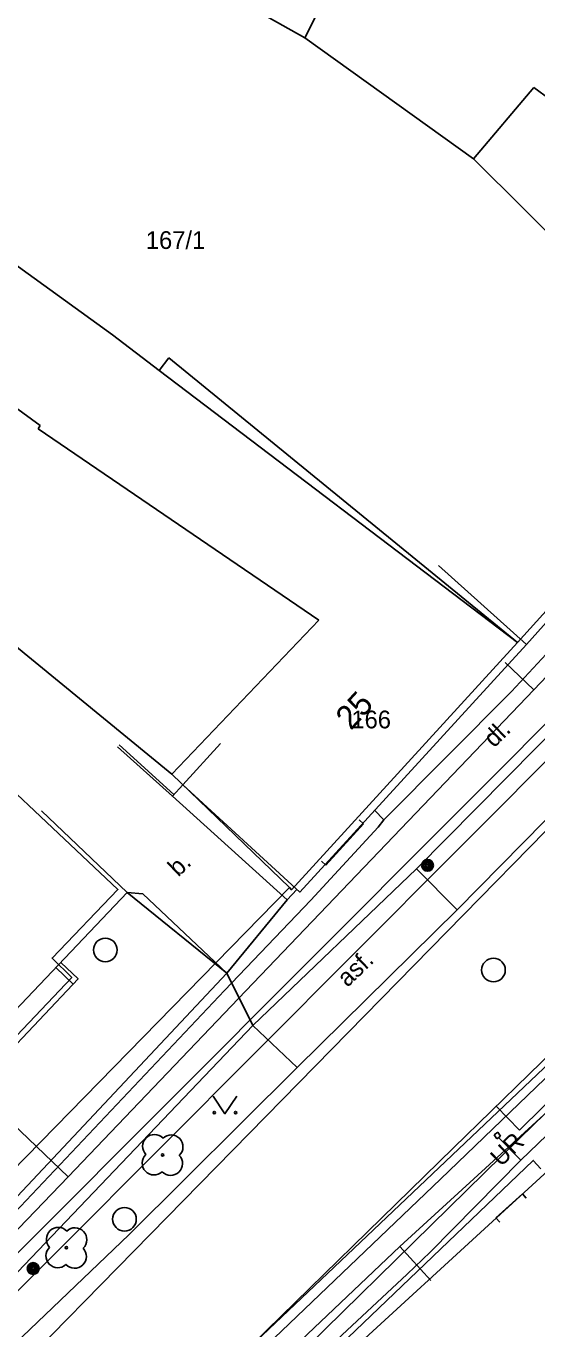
# Model space of a CAD drawing. Extents: x -601580 to 4, y -1204314 to 4.
# Drawn here: x -600441.7 to -600420.1, y -1203687.1 to -1203632.1 of the extents above; entities that cross this region are included whole.
import ezdxf

# ---------------------------------------------------------------- set-up
doc = ezdxf.new("R2010")
doc.units = 0
for name, color, linetype in [('00-INNOGY-NTL', 7, 'Continuous'), ('00-KN-HRANICE PARCEL', 7, 'Continuous'), ('00-KN-PARC. CISLA', 7, 'Continuous'), ('00-KN-VNITRNI KRESBA', 7, 'Continuous'), ('00-POLOHOPIS', 7, 'Continuous'), ('00-SITE KOM. KABEL', 7, 'Continuous'), ('00-VAK-VODA-RAD IGIS', 7, 'Continuous'), ('Vrstva 22', 7, 'Continuous'), ('Vrstva 25', 7, 'Continuous'), ('Vrstva 27', 7, 'Continuous'), ('Vrstva 36', 7, 'Continuous'), ('Vrstva 6', 7, 'Continuous')]:
    doc.layers.add(name, color=color, linetype=linetype)

# ---------------------------------------------------------------- blocks, each defined once
blk = doc.blocks.new('6.01A_68')
at = {"layer": 'Vrstva 25'}
for radius in [0.25, 0.2, 0.15, 0.1, 0.05]:
    blk.add_circle((0, 0), radius, dxfattribs=at)
blk = doc.blocks.new('6.01A_70')
at = {"layer": 'Vrstva 25'}
for radius in [0.25, 0.2, 0.15, 0.1, 0.05]:
    blk.add_circle((0, 0), radius, dxfattribs=at)
blk = doc.blocks.new('6.01A_72')
at = {"layer": 'Vrstva 25'}
for radius in [0.25, 0.2, 0.15, 0.1, 0.05]:
    blk.add_circle((0, 0), radius, dxfattribs=at)
blk = doc.blocks.new('6.01A_74')
at = {"layer": 'Vrstva 25'}
for radius in [0.25, 0.2, 0.15, 0.1, 0.05]:
    blk.add_circle((0, 0), radius, dxfattribs=at)
blk = doc.blocks.new('VCHOD_1416')
at = {"layer": 'Vrstva 6'}
blk.add_line((0, 0.25), (0, 0), dxfattribs=at)
blk = doc.blocks.new('VCHOD_1418')
at = {"layer": 'Vrstva 6'}
blk.add_line((0, 0.25), (0, 0), dxfattribs=at)
blk = doc.blocks.new('6.20_332')
at = {"layer": 'Vrstva 27'}
blk.add_circle((0, 0), 0.5, dxfattribs=at)
blk = doc.blocks.new('6.20D_244')
at = {"layer": 'Vrstva 27'}
blk.add_circle((0, 0), 0.5, dxfattribs=at)
blk = doc.blocks.new('6.20D_246')
at = {"layer": 'Vrstva 27'}
blk.add_circle((0, 0), 0.5, dxfattribs=at)
blk = doc.blocks.new('3.13_882')
at = {"layer": 'Vrstva 22'}
blk.add_circle((0, 0), 0.05, dxfattribs=at)
for centre, start, end in [((0, 0.5), 359.9999, 179.9999), ((-0.5, 0), 89.9999, 269.9999), ((0.5, 0), 269.9999, 89.9999), ((0, -0.5), 179.9999, 359.9999)]:
    blk.add_arc(centre, 0.5, start, end, dxfattribs=at)
blk = doc.blocks.new('3.13_884')
at = {"layer": 'Vrstva 22'}
blk.add_circle((0, 0), 0.05, dxfattribs=at)
for centre, start, end in [((0, 0.5), 359.9999, 179.9999), ((-0.5, 0), 89.9999, 269.9999), ((0.5, 0), 269.9999, 89.9999), ((0, -0.5), 179.9999, 359.9999)]:
    blk.add_arc(centre, 0.5, start, end, dxfattribs=at)
blk = doc.blocks.new('VCHOD_1432')
at = {"layer": 'Vrstva 6'}
blk.add_line((0, 0.25), (0, 0), dxfattribs=at)
blk = doc.blocks.new('VCHOD_1434')
at = {"layer": 'Vrstva 6'}
blk.add_line((0, 0.25), (0, 0), dxfattribs=at)
blk = doc.blocks.new('3.14_498')
at = {"layer": 'Vrstva 36'}
blk.add_lwpolyline([(-0.5, 0.75), (0, 0), (0.5, 0.75)], dxfattribs=at)
for centre in [(-0.45, 0.05), (0.449, 0.05)]:
    blk.add_circle(centre, 0.05, dxfattribs=at)

msp = doc.modelspace()

# ---------------------------------------------------------------- linework, layer by layer
at = {"layer": '00-INNOGY-NTL'}
for p, q in [((-600421.47, -1203658.98), (-600420.27, -1203660.14)), ((-600444.5, -1203676.34), (-600439.94, -1203680.7)), ((-600425.93, -1203683.63), (-600424.61, -1203685.07))]:
    msp.add_line(p, q, dxfattribs=at)
for points in [[(-600388.25, -1203628.77), (-600399.65, -1203639.6), (-600410.04, -1203649.48), (-600410.35, -1203649.77), (-600417.47, -1203657.21), (-600420.27, -1203660.14), (-600432.74, -1203673.17), (-600439.94, -1203680.7), (-600445.87, -1203686.85)], [(-600368.49, -1203630.18), (-600377.69, -1203636.35), (-600377.83, -1203636.45), (-600379.12, -1203637.4), (-600390.52, -1203649.08), (-600393.75, -1203652.39), (-600407.12, -1203666.06), (-600410.69, -1203669.71), (-600416.55, -1203675.06), (-600425.93, -1203683.63), (-600443.216, -1203700.032)]]:
    msp.add_lwpolyline(points, dxfattribs=at)
at = {"layer": '00-KN-HRANICE PARCEL'}
for p, q in [((-600438.07, -1203645.15), (-600443.46, -1203641.26)), ((-600448.84, -1203687.11), (-600430.59, -1203668.48))]:
    msp.add_line(p, q, dxfattribs=at)
for points in [[(-600468.32, -1203708.8), (-600459.02, -1203700.91), (-600447.7, -1203689.53), (-600417.71, -1203659.51), (-600398.8, -1203640.57), (-600381.76, -1203623.36), (-600376.64, -1203618.38), (-600366.85, -1203610.56), (-600358.79, -1203604.64), (-600335.27, -1203586.75), (-600326.92, -1203580.15), (-600315.47, -1203571.41), (-600313.87, -1203569.96), (-600309.19, -1203565.44), (-600307.64, -1203563.87), (-600297.75, -1203553.71), (-600294.09, -1203550.64), (-600277.89, -1203537.3), (-600263.22, -1203524.94), (-600248.8, -1203512.9), (-600231.21, -1203497.85)], [(-600468.32, -1203708.8), (-600459.02, -1203700.91), (-600447.7, -1203689.53), (-600417.71, -1203659.51), (-600398.8, -1203640.57), (-600381.76, -1203623.36), (-600376.64, -1203618.38), (-600366.85, -1203610.56), (-600358.79, -1203604.64), (-600335.27, -1203586.75), (-600326.92, -1203580.15), (-600315.47, -1203571.41), (-600313.87, -1203569.96), (-600309.19, -1203565.44), (-600307.64, -1203563.87), (-600297.75, -1203553.71), (-600294.09, -1203550.64), (-600277.89, -1203537.3), (-600263.22, -1203524.94), (-600248.8, -1203512.9), (-600231.21, -1203497.85)], [(-600253.46, -1203531.77), (-600259.57, -1203537.67), (-600309.35, -1203581.63), (-600334.21, -1203600.46), (-600346.34, -1203609.78), (-600356.33, -1203617.3), (-600362.86, -1203622.3), (-600365.25, -1203624.15), (-600378.09, -1203636.25), (-600381.77, -1203639.93), (-600406.92, -1203664.19), (-600424.21, -1203680.79), (-600450.71, -1203706.1), (-600456.83, -1203710.5), (-600463.46, -1203715.87), (-600472.33, -1203722.55), (-600482.23, -1203729.97), (-600500.93, -1203742.85), (-600516.74, -1203754.05)], [(-600437.73, -1203628.23), (-600429.94, -1203632.61), (-600422.81, -1203637.72), (-600412.1, -1203648.35)], [(-600430.59, -1203668.48), (-600435.56, -1203663.69), (-600446.11, -1203655.07), (-600451.09, -1203650.36), (-600457.96, -1203645.05)], [(-600420.96, -1203658.14), (-600436.09, -1203646.65), (-600438.07, -1203645.15)], [(-600420.96, -1203658.14), (-600416.39, -1203653.09), (-600412.1, -1203648.35)], [(-600430.59, -1203668.48), (-600430.51, -1203668.57), (-600420.96, -1203658.14)], [(-600457.99, -1203674.31), (-600452.79, -1203668.81), (-600453.42, -1203668.19), (-600451.54, -1203666.19), (-600450.87, -1203666.76), (-600445.65, -1203661.21), (-600437.84, -1203668.56), (-600440.62, -1203671.46), (-600439.79, -1203672.28), (-600446.52, -1203679.36), (-600447.21, -1203678.64), (-600450.16, -1203681.49)], [(-600419.97, -1203680.36), (-600420.29, -1203680), (-600437.57, -1203696.53)]]:
    msp.add_lwpolyline(points, dxfattribs=at)
at = {"layer": '00-KN-VNITRNI KRESBA'}
for p, q in [((-600427.13, -1203627), (-600429.94, -1203632.61)), ((-600420.26, -1203634.71), (-600422.81, -1203637.72)), ((-600417.85, -1203636.49), (-600420.26, -1203634.71)), ((-600435.69, -1203646.12), (-600436.09, -1203646.65)), ((-600435.69, -1203646.12), (-600420.96, -1203658.14)), ((-600441.12, -1203648.97), (-600443.73, -1203647.08)), ((-600441.21, -1203649.12), (-600441.12, -1203648.97)), ((-600429.35, -1203657.19), (-600441.21, -1203649.12)), ((-600435.56, -1203663.69), (-600429.35, -1203657.19))]:
    msp.add_line(p, q, dxfattribs=at)
at = {"layer": '00-POLOHOPIS'}
for p, q in [((-600423.502, -1203669.423), (-600411.699, -1203657.438)), ((-600418.174, -1203660.562), (-600425.223, -1203667.684)), ((-600437.855, -1203662.536), (-600435.537, -1203664.625)), ((-600437.788, -1203662.462), (-600435.469, -1203664.551)), ((-600429.057, -1203667.532), (-600427.466, -1203665.795)), ((-600425.223, -1203667.684), (-600432.138, -1203674.299)), ((-600423.502, -1203669.423), (-600425.223, -1203667.684)), ((-600437.445, -1203668.688), (-600433.239, -1203672.095)), ((-600436.784, -1203668.749), (-600437.445, -1203668.688)), ((-600433.239, -1203672.095), (-600436.784, -1203668.749)), ((-600430.681, -1203669.001), (-600433.239, -1203672.095)), ((-600430.266, -1203676.073), (-600423.502, -1203669.423)), ((-600423.652, -1203679.468), (-600414.526, -1203670.569)), ((-600440.462, -1203671.858), (-600439.731, -1203672.554)), ((-600413.668, -1203671.611), (-600420.867, -1203678.726)), ((-600433.239, -1203672.095), (-600447.539, -1203687.303)), ((-600433.239, -1203672.095), (-600432.138, -1203674.299)), ((-600445.943, -1203688.763), (-600432.138, -1203674.299)), ((-600432.138, -1203674.299), (-600430.266, -1203676.073)), ((-600430.266, -1203676.073), (-600437.375, -1203683.135)), ((-600421.854, -1203677.714), (-600420.867, -1203678.726)), ((-600421.945, -1203678.921), (-600421.78, -1203678.808)), ((-600421.945, -1203678.921), (-600421.832, -1203679.087)), ((-600421.832, -1203679.087), (-600421.667, -1203678.974)), ((-600421.667, -1203678.974), (-600421.78, -1203678.808)), ((-600439.757, -1203695.152), (-600423.652, -1203679.468)), ((-600421.868, -1203682.427), (-600420.75, -1203681.415)), ((-600437.375, -1203683.135), (-600455.775, -1203700.66))]:
    msp.add_line(p, q, dxfattribs=at)
for points in [[(-600415.367, -1203644.747), (-600411.831, -1203648.282), (-600411.749, -1203648.355), (-600420.573, -1203658.218), (-600424.299, -1203654.884)], [(-600424.299, -1203654.884), (-600420.573, -1203658.218), (-600430.148, -1203668.67), (-600435.093, -1203664.14), (-600433.499, -1203662.4)], [(-600430.273, -1203668.556), (-600430.681, -1203669.001), (-600435.537, -1203664.625), (-600435.093, -1203664.14)], [(-600441.066, -1203665.24), (-600437.445, -1203668.688), (-600449.877, -1203681.747), (-600453.498, -1203678.3)], [(-600440.256, -1203671.64), (-600439.525, -1203672.336), (-600442.829, -1203675.826), (-600446.3, -1203679.439), (-600447.024, -1203678.75)], [(-600416.279, -1203684.112), (-600419.655, -1203680.424), (-600437.335, -1203696.604), (-600433.959, -1203700.292)]]:
    msp.add_lwpolyline(points, dxfattribs=at)
at = {"layer": '00-SITE KOM. KABEL'}
for points in [[(-600421.21, -1203660.21), (-600415.71, -1203654.29), (-600409.87, -1203647.71)], [(-600426.6, -1203665.62), (-600421.21, -1203660.21), (-600415.71, -1203654.29)], [(-600426.6, -1203665.62), (-600426.99, -1203665.22)], [(-600445.32, -1203685.49), (-600433.34, -1203672.82), (-600429.69, -1203669.02), (-600426.84, -1203665.93), (-600426.6, -1203665.62)], [(-600433.34, -1203672.82), (-600429.69, -1203669.02), (-600426.84, -1203665.93)], [(-600433.58, -1203691.53), (-600420.86, -1203679.06), (-600412.83, -1203671.25)], [(-600420.82, -1203679.99), (-600412.82, -1203672.3)], [(-600421.75, -1203679.05), (-600420.82, -1203679.99)], [(-600433.06, -1203691.99), (-600428.59, -1203687.58), (-600425.61, -1203684.8), (-600424.64, -1203683.87), (-600420.82, -1203679.99)], [(-600424.64, -1203683.87), (-600425.61, -1203684.8)]]:
    msp.add_lwpolyline(points, dxfattribs=at)
at = {"layer": '00-VAK-VODA-RAD IGIS'}
for points in [[(-600370.99, -1203614.286), (-600423.616, -1203667.016)], [(-600372.217, -1203617.987), (-600384.278, -1203629.562), (-600410.006, -1203656.146), (-600451.093, -1203698.017), (-600454.254, -1203701.013)], [(-600423.616, -1203667.016), (-600452.716, -1203696.175)], [(-600450.006, -1203704.697), (-600416.253, -1203672.702)]]:
    msp.add_lwpolyline(points, dxfattribs=at)

# ---------------------------------------------------------------- block references
at = {"layer": '00-POLOHOPIS'}
for name, p, xscale, yscale, rotation in [('VCHOD_1434', (-600427.466, -1203665.795), 1.0000008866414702, 1.0000008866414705, 47.51185926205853), ('VCHOD_1432', (-600429.057, -1203667.532), 1.0000008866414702, 1.0000008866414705, 47.51185926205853), ('6.20D_244', (-600438.37, -1203671.115), 1.0000019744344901, 1.0000019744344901, 43.565852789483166), ('6.20_332', (-600421.971, -1203671.963), 1.0000011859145, 1.0000011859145, 44.29647215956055), ('3.13_882', (-600435.951, -1203679.77), 1.0000019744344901, 1.0000019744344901, 43.565852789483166), ('6.20D_246', (-600437.561, -1203682.485), 1.0000019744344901, 1.0000019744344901, 43.565852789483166), ('VCHOD_1418', (-600420.75, -1203681.415), 1.0000027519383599, 1.0000027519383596, -137.84898004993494), ('3.13_884', (-600440.016, -1203683.688), 1.0000019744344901, 1.0000019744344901, 43.565852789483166), ('VCHOD_1416', (-600421.868, -1203682.427), 1.0000027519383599, 1.0000027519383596, -137.84898004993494)]:
    msp.add_blockref(name, p, dxfattribs=dict(at, xscale=xscale, yscale=yscale, rotation=rotation))
at = {"layer": '00-POLOHOPIS', "rotation": 180}
for name, p in [('6.01A_68', (-600424.756, -1203667.543)), ('6.01A_70', (-600424.756, -1203667.543)), ('6.01A_72', (-600441.42, -1203684.565)), ('6.01A_74', (-600441.42, -1203684.565))]:
    msp.add_blockref(name, p, dxfattribs=at)
at = {"layer": '00-POLOHOPIS'}
msp.add_blockref('3.14_498', (-600433.318, -1203678.032), dxfattribs=at)

# ---------------------------------------------------------------- texts
at = {"layer": '00-KN-PARC. CISLA'}
for s, p in [('167/1', (-600436.659, -1203641.52)), ('166', (-600427.974, -1203661.76))]:
    msp.add_text(s, height=0.75, dxfattribs=at).set_placement(p)
at = {"layer": '00-POLOHOPIS'}
for s, height, rotation, p in [('25', 1, 47.5074, (-600427.992, -1203661.876)), ('dl.', 0.75, 44.2964, (-600421.946, -1203662.607)), ('b.', 0.75, 43.5658, (-600435.29, -1203668.058)), ('asf.', 0.75, 43.5658, (-600428.143, -1203672.716)), ('UR', 0.75, 44.2964, (-600421.654, -1203680.301))]:
    msp.add_text(s, height=height, rotation=rotation, dxfattribs=at).set_placement(p)

doc.saveas('drawing.dxf')
